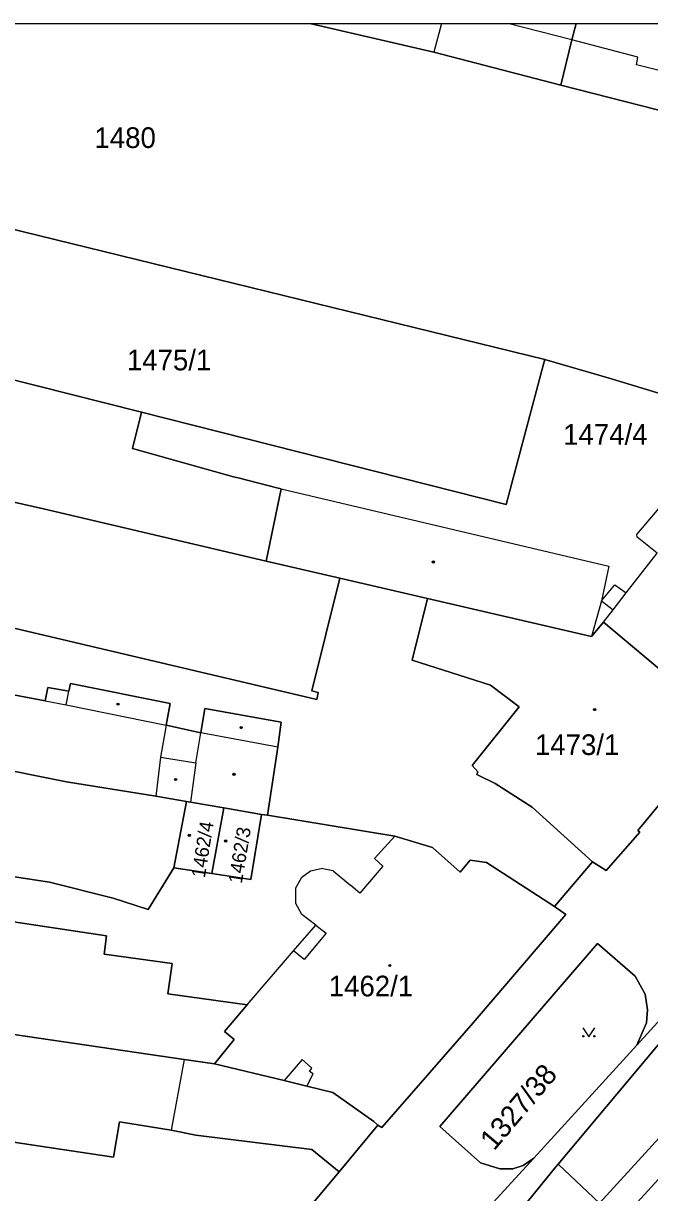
# Model space of a CAD drawing. Extents: x -598934 to -598196, y -1162208 to -1161502.
# Drawn here: x -598496.8 to -598445.3, y -1161601.3 to -1161505.2 of the extents above; entities that cross this region are included whole.
import ezdxf

# ---------------------------------------------------------------- set-up
doc = ezdxf.new("R2010")
doc.units = 0
for name, color, linetype in [('KN_CAR_KR', 7, 'Continuous'), ('KN_KULTURY', 7, 'Continuous'), ('KN_PARC_CIS_POZ', 7, 'Continuous'), ('KN_PARC_CIS_STAV', 7, 'Continuous'), ('KN_PARC_PLOCHA', 7, 'Continuous'), ('parcely_l', 7, 'Continuous')]:
    doc.layers.add(name, color=color, linetype=linetype)

msp = doc.modelspace()

# ---------------------------------------------------------------- linework, layer by layer
at = {"layer": 'KN_CAR_KR'}
for points in [[(-598462.418, -1161505.182), (-598463.04, -1161507.56)], [(-598451.68, -1161506.54), (-598456.953, -1161505.182)], [(-598446.25, -1161507.95), (-598451.68, -1161506.54)], [(-598446.37, -1161508.58), (-598446.25, -1161507.95)], [(-598442.18, -1161509.64), (-598446.37, -1161508.58)], [(-598475.62, -1161543.46), (-598448.64, -1161549.83)], [(-598446.32, -1161547.21), (-598443.55, -1161543.97)], [(-598446.3, -1161547.45), (-598446.32, -1161547.21)], [(-598444.66, -1161548.75), (-598446.3, -1161547.45)], [(-598447.2, -1161552.02), (-598444.66, -1161548.75)], [(-598448.64, -1161549.83), (-598449.23, -1161552.69)], [(-598449.23, -1161552.69), (-598448.14, -1161551.36)], [(-598448.14, -1161551.36), (-598447.2, -1161552.02)], [(-598449.23, -1161552.69), (-598450.06, -1161555.62)], [(-598449.23, -1161552.69), (-598448.28, -1161553.42)], [(-598448.28, -1161553.42), (-598447.2, -1161552.02)], [(-598449.07, -1161554.44), (-598448.28, -1161553.42)], [(-598493.32, -1161561.24), (-598493.1, -1161560.11)], [(-598495.04, -1161560.91), (-598493.32, -1161561.24)], [(-598493.32, -1161561.24), (-598485.07, -1161562.91)], [(-598485.07, -1161562.91), (-598485.56, -1161565.54)], [(-598482.64, -1161565.99), (-598482.22, -1161563.54)], [(-598475.88, -1161564.72), (-598482.22, -1161563.54)], [(-598485.56, -1161565.54), (-598485.93, -1161568.74)], [(-598485.56, -1161565.54), (-598482.64, -1161565.99)], [(-598482.64, -1161565.99), (-598483.09, -1161569.24)], [(-598467.94, -1161573.88), (-598466.25, -1161572.03)], [(-598473.2, -1161574.89), (-598472.32, -1161574.69)], [(-598471.32, -1161574.88), (-598472.32, -1161574.69)], [(-598467.24, -1161574.5), (-598469.14, -1161576.71)], [(-598467.94, -1161573.88), (-598467.24, -1161574.5)], [(-598474.43, -1161576.34), (-598473.92, -1161575.41)], [(-598473.92, -1161575.41), (-598473.2, -1161574.89)], [(-598471.32, -1161574.88), (-598469.89, -1161576.08)], [(-598474.43, -1161576.34), (-598474.44, -1161577.51)], [(-598469.14, -1161576.71), (-598469.89, -1161576.08)], [(-598473.92, -1161578.48), (-598474.44, -1161577.51)], [(-598472.77, -1161579.36), (-598473.92, -1161578.48)], [(-598474.6, -1161581.45), (-598472.77, -1161579.36)], [(-598472.77, -1161579.36), (-598471.9, -1161580.01)], [(-598471.9, -1161580.01), (-598473.73, -1161582.19)], [(-598478.41, -1161585.91), (-598474.6, -1161581.45)], [(-598473.73, -1161582.19), (-598474.6, -1161581.45)], [(-598483.61, -1161590.39), (-598484.67, -1161596.22)], [(-598473.88, -1161590.4), (-598475.38, -1161592.14)], [(-598473.08, -1161591.12), (-598473.88, -1161590.4)], [(-598473.27, -1161591.4), (-598473.08, -1161591.12)], [(-598473.5, -1161592.6), (-598472.99, -1161591.59)], [(-598472.99, -1161591.59), (-598473.27, -1161591.4)]]:
    msp.add_lwpolyline(points, dxfattribs=at)
at = {"layer": 'KN_KULTURY'}
msp.add_lwpolyline([(-598450.782, -1161587.792), (-598450.282, -1161588.542), (-598449.782, -1161587.792)], dxfattribs=at)
for centre, radius in [((-598463.08, -1161549.48), 0.09), ((-598463.08, -1161549.48), 0.0398), ((-598489.04, -1161561.18), 0.09), ((-598489.04, -1161561.18), 0.0398), ((-598449.8, -1161561.62), 0.09), ((-598449.8, -1161561.62), 0.0398), ((-598478.91, -1161563.1), 0.09), ((-598478.91, -1161563.1), 0.0398), ((-598479.49, -1161566.95), 0.09), ((-598479.49, -1161566.95), 0.0398), ((-598484.3, -1161567.37), 0.09), ((-598484.3, -1161567.37), 0.0398), ((-598483.18, -1161571.96), 0.09), ((-598483.18, -1161571.96), 0.0398), ((-598480.18, -1161572.43), 0.09), ((-598480.18, -1161572.43), 0.0398), ((-598466.67, -1161582.67), 0.09), ((-598466.67, -1161582.67), 0.0398), ((-598450.732, -1161588.491), 0.05), ((-598449.833, -1161588.491), 0.05)]:
    msp.add_circle(centre, radius, dxfattribs=at)
at = {"layer": 'KN_PARC_PLOCHA'}
for points in [[(-598452.58, -1161510.27), (-598432.7, -1161515.34), (-598432.44, -1161515.39), (-598431.41, -1161515.69), (-598431.94, -1161517.83), (-598432.44, -1161520.09), (-598439.28, -1161536.83), (-598437.38, -1161537.4), (-598437.42, -1161537.71), (-598438.48, -1161537.42), (-598439.92, -1161536.99), (-598448.61, -1161534.37), (-598453.91, -1161532.83), (-598501, -1161521.32), (-598508.64, -1161519.48), (-598509.92, -1161519.2), (-598513.33, -1161518.18), (-598513.61, -1161518.09), (-598516.94, -1161517.41), (-598523.46, -1161516.17), (-598547.13, -1161510.79), (-598545.465, -1161505.182), (-598473.242, -1161505.182), (-598463.04, -1161507.56)], [(-598452.58, -1161510.27), (-598463.04, -1161507.56), (-598473.242, -1161505.182), (-598451.316, -1161505.182), (-598451.68, -1161506.54)], [(-598423.63, -1161505.86), (-598426.49, -1161516.89), (-598427.96, -1161516.51), (-598431.41, -1161515.69), (-598432.44, -1161515.39), (-598432.7, -1161515.34), (-598452.58, -1161510.27), (-598451.68, -1161506.54), (-598451.316, -1161505.182), (-598426.093, -1161505.182)], [(-598516.94, -1161517.41), (-598516.99, -1161517.8), (-598518.58, -1161525.18), (-598515.62, -1161526.11), (-598509.86, -1161527.91), (-598510.29, -1161530.22), (-598498.76, -1161534.23), (-598487.12, -1161537.17), (-598487.86, -1161540.15), (-598479.54, -1161542.47), (-598479.04, -1161542.59), (-598475.96, -1161543.39), (-598475.62, -1161543.46), (-598476.84, -1161549.41), (-598495.18, -1161545.1), (-598528.11, -1161537.69), (-598523.46, -1161516.17)], [(-598453.91, -1161532.83), (-598454.02, -1161533.2), (-598457.1, -1161544.74), (-598487.12, -1161537.17), (-598498.76, -1161534.23), (-598510.29, -1161530.22), (-598509.86, -1161527.91), (-598515.62, -1161526.11), (-598513.33, -1161518.18), (-598509.92, -1161519.2), (-598508.64, -1161519.48), (-598501, -1161521.32)], [(-598528.11, -1161537.69), (-598495.18, -1161545.1), (-598476.84, -1161549.41), (-598470.79, -1161550.81), (-598473.08, -1161560.09), (-598472.57, -1161560.22), (-598472.69, -1161560.78), (-598539.92, -1161544.98), (-598539.79, -1161544.4), (-598539.32, -1161544.51), (-598537.22, -1161535.57), (-598528.65, -1161537.6)], [(-598439.03, -1161562.84), (-598446.26, -1161571.57), (-598446.09, -1161571.7), (-598448.86, -1161574.86), (-598449.99, -1161574.14), (-598454.94, -1161569.65), (-598457.98, -1161567.69), (-598459.51, -1161566.96), (-598459.42, -1161566.73), (-598459.88, -1161566.21), (-598456.03, -1161561.39), (-598458.37, -1161559.6), (-598464.84, -1161557.55), (-598463.56, -1161552.48), (-598450.06, -1161555.62), (-598449.07, -1161554.44)], [(-598483.41, -1161569.18), (-598484.44, -1161574.63), (-598486.56, -1161578.07), (-598489.44, -1161577.14), (-598494.7, -1161575.82), (-598522.64, -1161571.56), (-598520.5, -1161562.11), (-598493.29, -1161567.56), (-598485.93, -1161568.74)], [(-598423.21, -1161568.79), (-598420.91, -1161571.06), (-598421.93, -1161572.17), (-598449.39, -1161602.22), (-598452.8, -1161599.01), (-598438.32, -1161581.74), (-598435.01, -1161576.84), (-598428.2, -1161569.42), (-598425.39, -1161566.34)], [(-598480.34, -1161569.71), (-598481.33, -1161575.1), (-598484.44, -1161574.63), (-598483.41, -1161569.18), (-598483.09, -1161569.24)], [(-598477.22, -1161570.24), (-598478.11, -1161575.59), (-598481.33, -1161575.1), (-598480.34, -1161569.71)], [(-598419.3, -1161572.65), (-598420.31, -1161573.75), (-598447.76, -1161603.75), (-598449.39, -1161602.22), (-598421.93, -1161572.17), (-598420.91, -1161571.06)], [(-598415.2, -1161576.69), (-598443.61, -1161607.65), (-598447.76, -1161603.75), (-598420.31, -1161573.75), (-598419.3, -1161572.65)], [(-598481.09, -1161590.76), (-598483.61, -1161590.39), (-598516.53, -1161585.58), (-598516.95, -1161585.5), (-598519.66, -1161584.96), (-598525.49, -1161583.72), (-598524.78, -1161580.36), (-598515.6, -1161582.14), (-598514.8, -1161576.5), (-598490, -1161580.22), (-598490.19, -1161581.73), (-598484.6, -1161582.5), (-598484.95, -1161585), (-598478.41, -1161585.91), (-598480.27, -1161588.1), (-598479.49, -1161588.76)], [(-598525.49, -1161583.72), (-598519.66, -1161584.96), (-598516.95, -1161585.5), (-598516.53, -1161585.58), (-598483.61, -1161590.39), (-598481.09, -1161590.76), (-598475.38, -1161592.14), (-598473.5, -1161592.6), (-598471.37, -1161593.11), (-598467.99, -1161595.5), (-598467.65, -1161595.81), (-598470.85, -1161599.65), (-598473.08, -1161597.8), (-598482.63, -1161596.62), (-598484.67, -1161596.22), (-598488.92, -1161595.52), (-598489.42, -1161598.43), (-598502.44, -1161596.49), (-598505.36, -1161596), (-598521.03, -1161593.46), (-598537.42, -1161590.8), (-598537.22, -1161589.72), (-598535.61, -1161581.53)], [(-598446.33, -1161589.22), (-598454.81, -1161598.51), (-598455.7, -1161599.12), (-598456.55, -1161599.4), (-598457.62, -1161599.4), (-598459.21, -1161598.89), (-598462.55, -1161595.92), (-598449.57, -1161580.87), (-598446.48, -1161583.54), (-598445.65, -1161585.04), (-598445.45, -1161586.33), (-598445.53, -1161587.39)], [(-598449.39, -1161602.22), (-598457.13, -1161610.69), (-598502.88, -1161660.58), (-598453, -1161599.23), (-598452.8, -1161599.01)]]:
    msp.add_lwpolyline(points, close=True, dxfattribs=at)
for points in [[(-598439.03, -1161562.84), (-598449.07, -1161554.44), (-598450.06, -1161555.62), (-598463.56, -1161552.48), (-598470.79, -1161550.81), (-598476.84, -1161549.41), (-598475.62, -1161543.46), (-598475.96, -1161543.39), (-598479.04, -1161542.59), (-598479.54, -1161542.47), (-598487.86, -1161540.15), (-598487.12, -1161537.17), (-598457.1, -1161544.74), (-598454.02, -1161533.2), (-598453.91, -1161532.83), (-598448.61, -1161534.37), (-598439.92, -1161536.99)], [(-598539.92, -1161544.98), (-598472.69, -1161560.78), (-598472.57, -1161560.22), (-598473.08, -1161560.09), (-598470.79, -1161550.81), (-598463.56, -1161552.48), (-598464.84, -1161557.55), (-598458.37, -1161559.6), (-598456.03, -1161561.39), (-598459.88, -1161566.21), (-598459.42, -1161566.73), (-598459.51, -1161566.96), (-598457.98, -1161567.69), (-598454.94, -1161569.65), (-598449.99, -1161574.14), (-598453.12, -1161577.83), (-598458.72, -1161574.2), (-598460.05, -1161574.02), (-598460.88, -1161575), (-598463.15, -1161572.97), (-598466.25, -1161572.03), (-598476.73, -1161570.31), (-598475.88, -1161564.72), (-598475.6, -1161562.65), (-598481.91, -1161561.52), (-598482.22, -1161563.54), (-598485.07, -1161562.91), (-598484.76, -1161561.11), (-598492.97, -1161559.48), (-598493.1, -1161560.11), (-598494.82, -1161559.8), (-598495.04, -1161560.91), (-598516.82, -1161556.8)], [(-598516.82, -1161556.8), (-598495.04, -1161560.91), (-598494.82, -1161559.8), (-598493.1, -1161560.11), (-598492.97, -1161559.48), (-598484.76, -1161561.11), (-598485.07, -1161562.91), (-598482.22, -1161563.54), (-598481.91, -1161561.52), (-598475.6, -1161562.65), (-598475.88, -1161564.72), (-598476.73, -1161570.31), (-598477.22, -1161570.24), (-598480.34, -1161569.71), (-598483.09, -1161569.24), (-598483.41, -1161569.18), (-598485.93, -1161568.74), (-598493.29, -1161567.56), (-598520.5, -1161562.11)], [(-598483.87, -1161615.19), (-598470.85, -1161599.65), (-598467.65, -1161595.81), (-598467.33, -1161596), (-598459.81, -1161587.39), (-598452.17, -1161578.48), (-598453.12, -1161577.83), (-598449.99, -1161574.14), (-598448.86, -1161574.86), (-598446.09, -1161571.7), (-598446.26, -1161571.57), (-598439.03, -1161562.84)], [(-598522.64, -1161571.56), (-598494.7, -1161575.82), (-598489.44, -1161577.14), (-598486.56, -1161578.07), (-598484.44, -1161574.63), (-598481.33, -1161575.1), (-598478.11, -1161575.59), (-598477.22, -1161570.24), (-598476.73, -1161570.31), (-598466.25, -1161572.03), (-598463.15, -1161572.97), (-598460.88, -1161575), (-598460.05, -1161574.02), (-598458.72, -1161574.2), (-598453.12, -1161577.83), (-598452.17, -1161578.48), (-598459.81, -1161587.39), (-598467.33, -1161596), (-598467.65, -1161595.81), (-598467.99, -1161595.5), (-598471.37, -1161593.11), (-598473.5, -1161592.6), (-598475.38, -1161592.14), (-598481.09, -1161590.76), (-598479.49, -1161588.76), (-598480.27, -1161588.1), (-598478.41, -1161585.91), (-598484.95, -1161585), (-598484.6, -1161582.5), (-598490.19, -1161581.73), (-598490, -1161580.22), (-598514.8, -1161576.5)], [(-598553.66, -1161601.61), (-598579.26, -1161595.13), (-598573.22, -1161572.72), (-598554.41, -1161577.51), (-598539.27, -1161580.77), (-598536.29, -1161581.38), (-598536, -1161581.45), (-598535.61, -1161581.53), (-598537.22, -1161589.72), (-598537.42, -1161590.8), (-598521.03, -1161593.46), (-598505.36, -1161596), (-598502.44, -1161596.49), (-598489.42, -1161598.43), (-598488.92, -1161595.52), (-598484.67, -1161596.22), (-598482.63, -1161596.62), (-598473.08, -1161597.8), (-598470.85, -1161599.65), (-598483.87, -1161615.19)], [(-598601.64, -1161758.47), (-598594.41, -1161746.34), (-598574.71, -1161725.04), (-598562.49, -1161716.2), (-598546.26, -1161698.46), (-598538.27, -1161689.71), (-598508.71, -1161657.4), (-598500.6, -1161648.49), (-598493.91, -1161641.2), (-598488.42, -1161635.24), (-598481.9, -1161628.09), (-598472.12, -1161617.39), (-598454.81, -1161598.51), (-598446.33, -1161589.22), (-598435.01, -1161576.84), (-598438.32, -1161581.74), (-598452.8, -1161599.01), (-598453, -1161599.23), (-598502.88, -1161660.58), (-598537.16, -1161698.1), (-598569.06, -1161732.86), (-598601.28, -1161767.71)], [(-598435.01, -1161576.84), (-598446.33, -1161589.22), (-598445.53, -1161587.39), (-598445.45, -1161586.33), (-598445.65, -1161585.04), (-598446.48, -1161583.54), (-598449.57, -1161580.87), (-598462.55, -1161595.92), (-598459.21, -1161598.89), (-598457.62, -1161599.4), (-598456.55, -1161599.4), (-598455.7, -1161599.12), (-598454.81, -1161598.51), (-598472.12, -1161617.39)]]:
    msp.add_lwpolyline(points, dxfattribs=at)
at = {"layer": 'parcely_l'}
for points in [[(-598545.465, -1161505.182), (-598473.242, -1161505.182)], [(-598473.242, -1161505.182), (-598463.04, -1161507.56), (-598452.58, -1161510.27)], [(-598473.242, -1161505.182), (-598451.316, -1161505.182)], [(-598451.316, -1161505.182), (-598451.68, -1161506.54), (-598452.58, -1161510.27)], [(-598451.316, -1161505.182), (-598426.093, -1161505.182)], [(-598452.58, -1161510.27), (-598432.7, -1161515.34), (-598432.44, -1161515.39), (-598431.41, -1161515.69)], [(-598453.91, -1161532.83), (-598501, -1161521.32), (-598508.64, -1161519.48), (-598509.92, -1161519.2), (-598513.33, -1161518.18)], [(-598590.72, -1161526.69), (-598588.73, -1161527.17), (-598549.82, -1161537.87), (-598544.76, -1161539.24), (-598545.04, -1161540.92), (-598542.48, -1161541.59), (-598544.38, -1161550.34), (-598537.46, -1161551.8), (-598516.82, -1161556.8), (-598495.04, -1161560.91), (-598494.82, -1161559.8), (-598493.1, -1161560.11), (-598492.97, -1161559.48), (-598484.76, -1161561.11), (-598485.07, -1161562.91), (-598482.22, -1161563.54), (-598481.91, -1161561.52), (-598475.6, -1161562.65), (-598475.88, -1161564.72), (-598476.73, -1161570.31)], [(-598487.12, -1161537.17), (-598498.76, -1161534.23), (-598510.29, -1161530.22), (-598509.86, -1161527.91), (-598515.62, -1161526.11)], [(-598487.12, -1161537.17), (-598457.1, -1161544.74), (-598454.02, -1161533.2), (-598453.91, -1161532.83)], [(-598439.92, -1161536.99), (-598448.61, -1161534.37), (-598453.91, -1161532.83)], [(-598537.22, -1161535.57), (-598539.32, -1161544.51), (-598539.79, -1161544.4), (-598539.92, -1161544.98), (-598472.69, -1161560.78), (-598472.57, -1161560.22), (-598473.08, -1161560.09), (-598470.79, -1161550.81)], [(-598476.84, -1161549.41), (-598475.62, -1161543.46), (-598475.96, -1161543.39), (-598479.04, -1161542.59), (-598479.54, -1161542.47), (-598487.86, -1161540.15), (-598487.12, -1161537.17)], [(-598528.11, -1161537.69), (-598495.18, -1161545.1), (-598476.84, -1161549.41)], [(-598470.79, -1161550.81), (-598476.84, -1161549.41)], [(-598463.56, -1161552.48), (-598470.79, -1161550.81)], [(-598463.56, -1161552.48), (-598464.84, -1161557.55), (-598458.37, -1161559.6), (-598456.03, -1161561.39), (-598459.88, -1161566.21), (-598459.42, -1161566.73), (-598459.51, -1161566.96), (-598457.98, -1161567.69), (-598454.94, -1161569.65), (-598449.99, -1161574.14)], [(-598439.03, -1161562.84), (-598449.07, -1161554.44), (-598450.06, -1161555.62), (-598463.56, -1161552.48)], [(-598520.5, -1161562.11), (-598493.29, -1161567.56), (-598485.93, -1161568.74), (-598483.41, -1161569.18)], [(-598449.99, -1161574.14), (-598448.86, -1161574.86), (-598446.09, -1161571.7), (-598446.26, -1161571.57), (-598439.03, -1161562.84)], [(-598483.41, -1161569.18), (-598484.44, -1161574.63)], [(-598480.34, -1161569.71), (-598483.09, -1161569.24), (-598483.41, -1161569.18)], [(-598481.33, -1161575.1), (-598480.34, -1161569.71)], [(-598477.22, -1161570.24), (-598480.34, -1161569.71)], [(-598481.33, -1161575.1), (-598478.11, -1161575.59), (-598477.22, -1161570.24)], [(-598477.22, -1161570.24), (-598476.73, -1161570.31)], [(-598476.73, -1161570.31), (-598466.25, -1161572.03), (-598463.15, -1161572.97), (-598460.88, -1161575), (-598460.05, -1161574.02), (-598458.72, -1161574.2), (-598453.12, -1161577.83)], [(-598522.64, -1161571.56), (-598494.7, -1161575.82), (-598489.44, -1161577.14), (-598486.56, -1161578.07), (-598484.44, -1161574.63)], [(-598449.39, -1161602.22), (-598421.93, -1161572.17), (-598420.91, -1161571.06)], [(-598419.3, -1161572.65), (-598420.31, -1161573.75), (-598447.76, -1161603.75)], [(-598484.44, -1161574.63), (-598481.33, -1161575.1)], [(-598453.12, -1161577.83), (-598449.99, -1161574.14)], [(-598524.78, -1161580.36), (-598515.6, -1161582.14), (-598514.8, -1161576.5), (-598490, -1161580.22), (-598490.19, -1161581.73), (-598484.6, -1161582.5), (-598484.95, -1161585), (-598478.41, -1161585.91), (-598480.27, -1161588.1), (-598479.49, -1161588.76), (-598481.09, -1161590.76)], [(-598452.8, -1161599.01), (-598438.32, -1161581.74), (-598435.01, -1161576.84)], [(-598435.01, -1161576.84), (-598446.33, -1161589.22)], [(-598467.65, -1161595.81), (-598467.33, -1161596), (-598459.81, -1161587.39), (-598452.17, -1161578.48), (-598453.12, -1161577.83)], [(-598470.85, -1161599.65), (-598473.08, -1161597.8), (-598482.63, -1161596.62), (-598484.67, -1161596.22), (-598488.92, -1161595.52), (-598489.42, -1161598.43), (-598502.44, -1161596.49), (-598505.36, -1161596), (-598521.03, -1161593.46), (-598537.42, -1161590.8), (-598537.22, -1161589.72), (-598535.61, -1161581.53)], [(-598446.33, -1161589.22), (-598445.53, -1161587.39), (-598445.45, -1161586.33), (-598445.65, -1161585.04), (-598446.48, -1161583.54), (-598449.57, -1161580.87), (-598462.55, -1161595.92), (-598459.21, -1161598.89), (-598457.62, -1161599.4), (-598456.55, -1161599.4), (-598455.7, -1161599.12), (-598454.81, -1161598.51)], [(-598481.09, -1161590.76), (-598483.61, -1161590.39), (-598516.53, -1161585.58), (-598516.95, -1161585.5), (-598519.66, -1161584.96), (-598525.49, -1161583.72)], [(-598454.81, -1161598.51), (-598446.33, -1161589.22)], [(-598481.09, -1161590.76), (-598475.38, -1161592.14), (-598473.5, -1161592.6), (-598471.37, -1161593.11), (-598467.99, -1161595.5), (-598467.65, -1161595.81)], [(-598467.65, -1161595.81), (-598470.85, -1161599.65)], [(-598454.81, -1161598.51), (-598472.12, -1161617.39)], [(-598502.88, -1161660.58), (-598453, -1161599.23), (-598452.8, -1161599.01)], [(-598483.87, -1161615.19), (-598470.85, -1161599.65)], [(-598452.8, -1161599.01), (-598449.39, -1161602.22)]]:
    msp.add_lwpolyline(points, dxfattribs=at)

# ---------------------------------------------------------------- texts
at = {"layer": 'KN_PARC_CIS_POZ'}
for s, p in [('1480', (-598490.987, -1161515.43)), ('1475/1', (-598488.317, -1161533.72)), ('1474/4', (-598452.397, -1161539.84))]:
    msp.add_text(s, height=1.7, dxfattribs=at).set_placement(p)
msp.add_text('1327/38', height=1.7, rotation=49.87312, dxfattribs=at).set_placement((-598458.082, -1161597.973))
at = {"layer": 'KN_PARC_CIS_STAV'}
for s, p in [('1473/1', (-598454.722, -1161565.36)), ('1462/1', (-598471.697, -1161585.21))]:
    msp.add_text(s, height=1.7, dxfattribs=at).set_placement(p)
for s, rotation, p in [('1462/4', 80.91256, (-598481.9, -1161575.519)), ('1462/3', 80.56601, (-598478.859, -1161575.986))]:
    msp.add_text(s, height=1.14, rotation=rotation, dxfattribs=at).set_placement(p)

doc.saveas('drawing.dxf')
